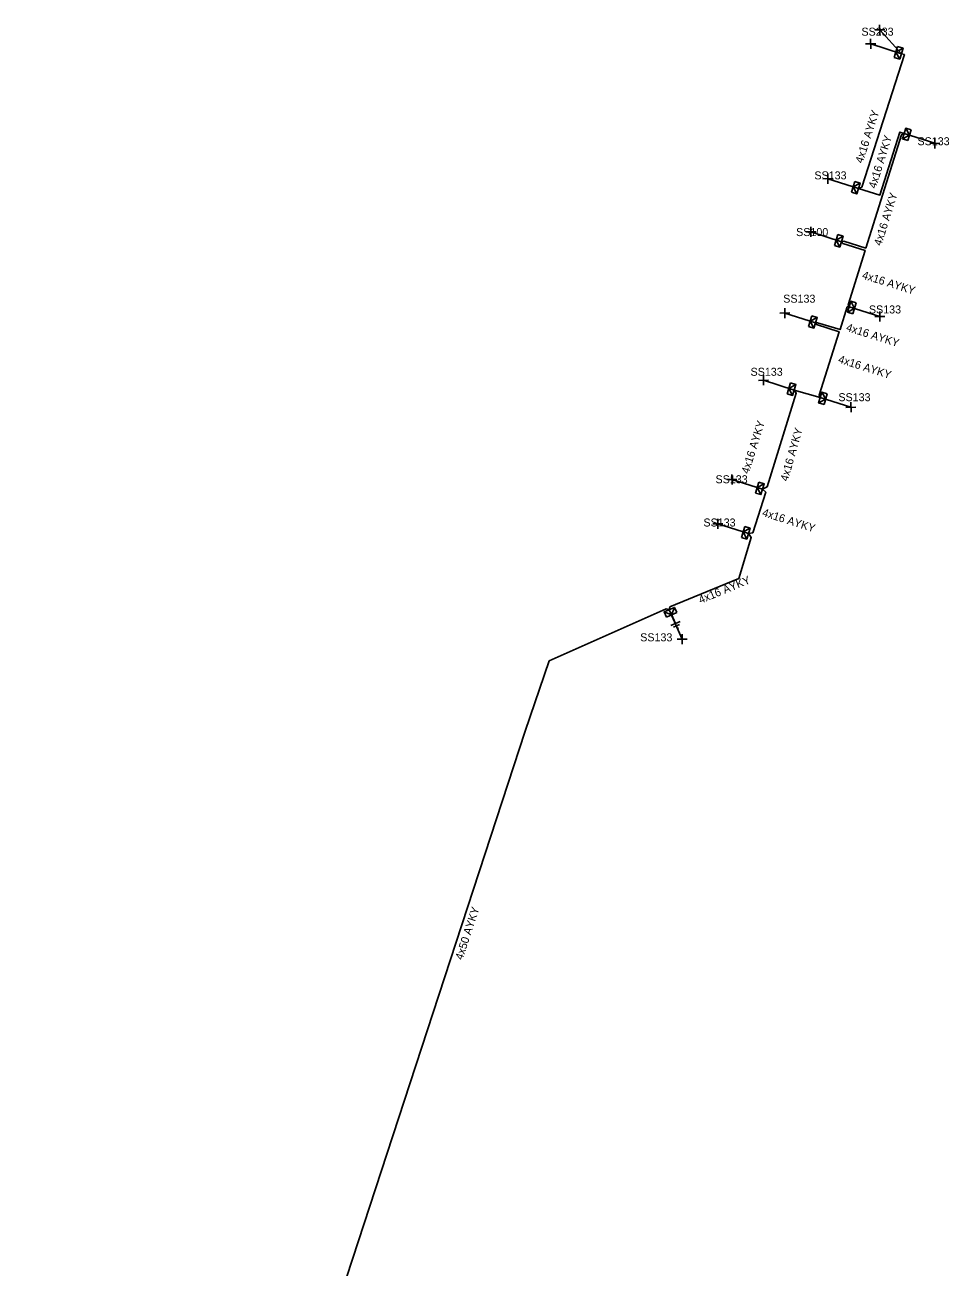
# Model space of a CAD drawing. Extents: x -762500 to -761285, y -1155006 to -1154135.
# Drawn here: x -761865.8 to -761751, y -1154289.3 to -1154135 of the extents above; entities that cross this region are included whole.
import ezdxf

# ---------------------------------------------------------------- set-up
doc = ezdxf.new("R2010")
doc.units = 0
for name, color, linetype in [('Vrstva 15', 7, 'Continuous'), ('Vrstva 31', 7, 'Continuous'), ('Vrstva 33', 7, 'Continuous'), ('Vrstva 34', 7, 'Continuous'), ('Vrstva 5', 7, 'Continuous'), ('Vrstva 59', 7, 'Continuous'), ('Vrstva 6', 7, 'Continuous')]:
    doc.layers.add(name, color=color, linetype=linetype)

msp = doc.modelspace()

# ---------------------------------------------------------------- linework, layer by layer
at = {"layer": 'Vrstva 15'}
for points in [[(-761784.387, -1154209.141), (-761785.529, -1154209.649)], [(-761785.466, -1154208.253), (-761784.958, -1154209.395)], [(-761784.481, -1154209.522), (-761785.2, -1154209.842)], [(-761784.703, -1154209.966), (-761784.82, -1154210.018)], [(-761784.582, -1154209.912), (-761784.703, -1154209.966)]]:
    msp.add_lwpolyline(points, dxfattribs=at)
at = {"layer": 'Vrstva 31'}
for points in [[(-761757.375, -1154137.743), (-761757.784, -1154139.082)], [(-761757.375, -1154137.743), (-761756.705, -1154137.947), (-761757.115, -1154139.286), (-761757.784, -1154139.082)], [(-761757.579, -1154138.412), (-761756.705, -1154137.947)], [(-761757.579, -1154138.412), (-761757.115, -1154139.286)], [(-761756.116, -1154149.417), (-761756.785, -1154149.212), (-761756.376, -1154147.873), (-761755.706, -1154148.078)], [(-761755.911, -1154148.747), (-761756.785, -1154149.212)], [(-761755.911, -1154148.747), (-761756.376, -1154147.873)], [(-761756.116, -1154149.417), (-761755.706, -1154148.078)], [(-761762.704, -1154154.483), (-761763.113, -1154155.822)], [(-761762.704, -1154154.483), (-761762.034, -1154154.688), (-761762.444, -1154156.026), (-761763.113, -1154155.822)], [(-761762.908, -1154155.152), (-761762.034, -1154154.688)], [(-761762.908, -1154155.152), (-761762.444, -1154156.026)], [(-761764.815, -1154161.093), (-761765.224, -1154162.432)], [(-761764.815, -1154161.093), (-761764.145, -1154161.297), (-761764.554, -1154162.636), (-761765.224, -1154162.432)], [(-761765.019, -1154161.762), (-761764.145, -1154161.297)], [(-761765.019, -1154161.762), (-761764.554, -1154162.636)], [(-761762.926, -1154170.917), (-761763.595, -1154170.712), (-761763.186, -1154169.373), (-761762.516, -1154169.578)], [(-761762.721, -1154170.247), (-761763.595, -1154170.712)], [(-761762.721, -1154170.247), (-761763.186, -1154169.373)], [(-761762.926, -1154170.917), (-761762.516, -1154169.578)], [(-761768.024, -1154171.163), (-761768.433, -1154172.502)], [(-761768.024, -1154171.163), (-761767.355, -1154171.368), (-761767.764, -1154172.707), (-761768.433, -1154172.502)], [(-761768.229, -1154171.833), (-761767.355, -1154171.368)], [(-761768.229, -1154171.833), (-761767.764, -1154172.707)], [(-761770.684, -1154179.513), (-761771.093, -1154180.852)], [(-761770.684, -1154179.513), (-761770.015, -1154179.718), (-761770.424, -1154181.057), (-761771.093, -1154180.852)], [(-761770.889, -1154180.183), (-761770.015, -1154179.718)], [(-761770.889, -1154180.183), (-761770.424, -1154181.057)], [(-761766.516, -1154182.187), (-761767.186, -1154181.982), (-761766.776, -1154180.643), (-761766.107, -1154180.848)], [(-761766.311, -1154181.518), (-761766.776, -1154180.643)], [(-761766.516, -1154182.187), (-761766.107, -1154180.848)], [(-761766.311, -1154181.518), (-761767.186, -1154181.982)], [(-761774.604, -1154191.843), (-761775.014, -1154193.181)], [(-761774.604, -1154191.843), (-761773.935, -1154192.047), (-761774.344, -1154193.386), (-761775.014, -1154193.181)], [(-761774.809, -1154192.512), (-761773.935, -1154192.047)], [(-761774.809, -1154192.512), (-761774.344, -1154193.386)], [(-761776.364, -1154197.353), (-761776.773, -1154198.692)], [(-761776.364, -1154197.353), (-761775.694, -1154197.558), (-761776.104, -1154198.897), (-761776.773, -1154198.692)], [(-761776.569, -1154198.022), (-761775.694, -1154197.558)], [(-761776.569, -1154198.022), (-761776.104, -1154198.897)], [(-761786.087, -1154208.596), (-761786.372, -1154207.956), (-761785.093, -1154207.387), (-761784.808, -1154208.026)], [(-761785.448, -1154208.311), (-761785.093, -1154207.387)], [(-761785.448, -1154208.311), (-761786.372, -1154207.956)], [(-761786.087, -1154208.596), (-761784.808, -1154208.026)]]:
    msp.add_lwpolyline(points, dxfattribs=at)
at = {"layer": 'Vrstva 34'}
for points in [[(-761759.589, -1154136.285), (-761759.611, -1154135.035)], [(-761760.225, -1154135.671), (-761758.975, -1154135.649)], [(-761761.345, -1154137.411), (-761760.095, -1154137.389)], [(-761760.709, -1154138.025), (-761760.731, -1154136.775)], [(-761753.385, -1154149.761), (-761752.135, -1154149.739)], [(-761752.749, -1154150.375), (-761752.771, -1154149.125)], [(-761766.039, -1154154.765), (-761766.061, -1154153.515)], [(-761766.675, -1154154.151), (-761765.425, -1154154.129)], [(-761768.785, -1154160.761), (-761767.535, -1154160.739)], [(-761768.149, -1154161.375), (-761768.171, -1154160.125)], [(-761771.369, -1154171.455), (-761771.391, -1154170.205)], [(-761759.569, -1154171.875), (-761759.591, -1154170.625)], [(-761772.005, -1154170.841), (-761770.755, -1154170.819)], [(-761760.205, -1154171.261), (-761758.955, -1154171.239)], [(-761774.655, -1154179.191), (-761773.405, -1154179.169)], [(-761774.019, -1154179.805), (-761774.041, -1154178.555)], [(-761763.795, -1154182.541), (-761762.545, -1154182.519)], [(-761763.159, -1154183.155), (-761763.181, -1154181.905)], [(-761778.575, -1154191.511), (-761777.325, -1154191.489)], [(-761777.939, -1154192.125), (-761777.961, -1154190.875)], [(-761779.699, -1154197.635), (-761779.721, -1154196.385)], [(-761780.335, -1154197.021), (-761779.085, -1154196.999)], [(-761784.129, -1154211.965), (-761784.151, -1154210.715)], [(-761784.765, -1154211.351), (-761783.515, -1154211.329)]]:
    msp.add_lwpolyline(points, dxfattribs=at)
at = {"layer": 'Vrstva 5'}
for points in [[(-761785.73, -1154207.67), (-761785.66, -1154207.33), (-761777.08, -1154203.78), (-761775.55, -1154198.71), (-761775.9, -1154198.23), (-761775.37, -1154198.11), (-761773.76, -1154193.06), (-761774.14, -1154192.72), (-761773.58, -1154192.4), (-761769.96, -1154180.8), (-761770.22, -1154180.39), (-761766.98, -1154181.31), (-761767.12, -1154181.01), (-761764.64, -1154173.16), (-761767.44, -1154172.27), (-761767.56, -1154172.04), (-761767.33, -1154172.03), (-761764.53, -1154172.88), (-761763.64, -1154170.06), (-761763.4, -1154170.04), (-761763.53, -1154169.81), (-761761.42, -1154163.05), (-761764.17, -1154162.19), (-761764.35, -1154161.97), (-761764.07, -1154161.9), (-761761.33, -1154162.76), (-761756.91, -1154148.68), (-761756.58, -1154148.54), (-761757.12, -1154148.35), (-761759.58, -1154156.18), (-761762.24, -1154155.36), (-761761.84, -1154155.18), (-761756.53, -1154138.72), (-761756.91, -1154138.62)], [(-761865.76, -1154418.41), (-761865.2, -1154418.3), (-761860.7, -1154402.52), (-761853.63, -1154377.31), (-761842.77, -1154342.76), (-761828.01, -1154297.38), (-761842.58, -1154292.02), (-761842.88, -1154291.91), (-761843.3, -1154292.83), (-761843.49, -1154292.88), (-761843.56, -1154292.67), (-761843.04, -1154291.54), (-761827.94, -1154297.08), (-761803.61, -1154222.76), (-761800.64, -1154214.04), (-761786.13, -1154207.56), (-761785.73, -1154207.67)]]:
    msp.add_lwpolyline(points, dxfattribs=at)
at = {"layer": 'Vrstva 59'}
for points in [[(-761756.91, -1154138.62), (-761759.6, -1154135.66)], [(-761756.91, -1154138.62), (-761760.72, -1154137.4)], [(-761756.58, -1154148.54), (-761752.76, -1154149.75)], [(-761762.24, -1154155.36), (-761766.05, -1154154.14)], [(-761764.35, -1154161.97), (-761768.16, -1154160.75)], [(-761763.39, -1154170.04), (-761759.58, -1154171.25)], [(-761767.56, -1154172.04), (-761771.38, -1154170.83)], [(-761770.22, -1154180.39), (-761774.03, -1154179.18)], [(-761766.98, -1154181.31), (-761763.17, -1154182.53)], [(-761774.14, -1154192.72), (-761777.95, -1154191.5)], [(-761775.9, -1154198.23), (-761779.71, -1154197.01)], [(-761785.73, -1154207.67), (-761784.14, -1154211.34)]]:
    msp.add_lwpolyline(points, dxfattribs=at)

# ---------------------------------------------------------------- texts
at = {"layer": 'Vrstva 33'}
for s, p in [('SS233', (-761761.87, -1154136.38)), ('SS133', (-761754.91, -1154149.99)), ('SS133', (-761767.71, -1154154.23)), ('SS100', (-761769.98, -1154161.27)), ('SS133', (-761771.58, -1154169.54)), ('SS133', (-761760.94, -1154170.88)), ('SS133', (-761775.64, -1154178.62)), ('SS133', (-761764.73, -1154181.78)), ('SS133', (-761779.99, -1154191.97)), ('SS133', (-761781.49, -1154197.34)), ('SS133', (-761789.34, -1154211.6))]:
    msp.add_text(s, height=0.9943, dxfattribs=at).set_placement(p)
at = {"layer": 'Vrstva 6'}
for s, rotation, p in [('4x16 AYKY', 72.08998, (-761761.73, -1154152.3)), ('4x16 AYKY', 72.75516, (-761760.08, -1154155.43)), ('4x16 AYKY', 72.59918, (-761759.41, -1154162.55)), ('4x16 AYKY', 342.67973, (-761761.87, -1154166.52)), ('4x16 AYKY', 342.43459, (-761763.85, -1154173.01)), ('4x16 AYKY', 342.44124, (-761764.83, -1154176.97)), ('4x16 AYKY', 72.67129, (-761775.87, -1154190.87)), ('4x16 AYKY', 74.10127, (-761771.02, -1154191.8)), ('4x16 AYKY', 342.32366, (-761774.27, -1154196.01)), ('4x16 AYKY', 22.46135, (-761781.85, -1154206.95)), ('4x50 AYKY', 71.87276, (-761811.41, -1154251.24))]:
    msp.add_text(s, height=0.9943, rotation=rotation, dxfattribs=at).set_placement(p)

doc.saveas('drawing.dxf')
